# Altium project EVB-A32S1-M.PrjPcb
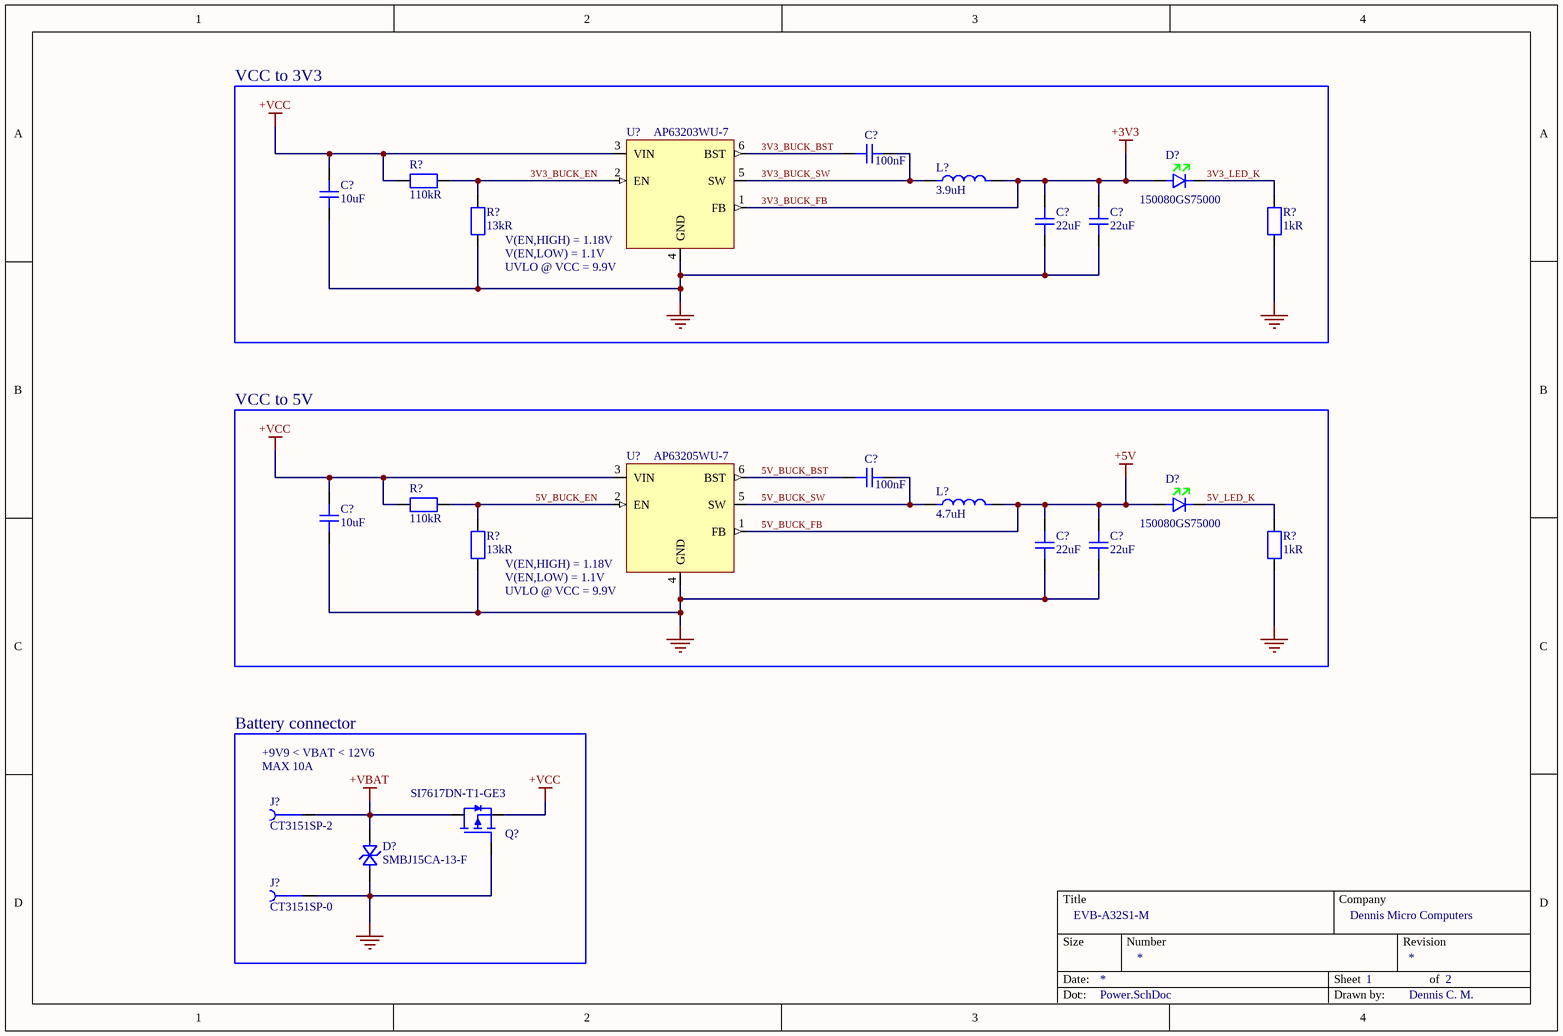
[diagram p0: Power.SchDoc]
CompanyName: Dennis Micro Computers; DrawnBy: Dennis C. M.; Title: EVB-A32S1-M
4 sheets, 55 parts. Net scope: flat (ports and power ports of the same name join across sheets).
Sheets:
  Power.SchDoc
  MCU.SchDoc
  Motor.SchDoc
  Sensing.SchDoc

## Sheet Power.SchDoc: EVB-A32S1-M
size A4; SheetNumber: 1; SheetTotal: 2

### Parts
(Parts that share a designator on the sheet are numbered #1, #2 ... from top to bottom, then left to right.)
C?#1  value 100nF  [C_Yageo_CC_0402_A]  (hidden comment: CC0402MRX5R6BB104)
C?#2  value 10uF  [C_Yageo_CC_0805_A]  (hidden comment: CC0805KRX5R7BB106)
C?#3  value 22uF  [C_Yageo_CC_0805_A]  (hidden comment: CC0805MKX5R6BB226)
C?#4  value 22uF  [C_Yageo_CC_0805_A]  (hidden comment: CC0805MKX5R6BB226)
C?#5  value 100nF  [C_Yageo_CC_0402_A]  (hidden comment: CC0402MRX5R6BB104)
C?#6  value 10uF  [C_Yageo_CC_0805_A]  (hidden comment: CC0805KRX5R7BB106)
C?#7  value 22uF  [C_Yageo_CC_0805_A]  (hidden comment: CC0805MKX5R6BB226)
C?#8  value 22uF  [C_Yageo_CC_0805_A]  (hidden comment: CC0805MKX5R6BB226)
D?#1  150080GS75000  [D_LED_We_150080GS75000]
D?#2  150080GS75000  [D_LED_We_150080GS75000]
D?#3  SMBJ15CA-13-F  [D_TVS_BI_Diodes_SMBJ15CA-13-F_A]
J?#1  CT3151SP-2  [J_CalTest_CT3151SP-2]
J?#2  CT3151SP-0  [J_CalTest_CT3151SP-0]
L?#1  value 3.9uH  [L_Murata_1255AY-XXXX=P3]  (hidden comment: 1255AY-3R9N=P3)
L?#2  value 4.7uH  [L_Murata_1255AY-XXXX=P3]  (hidden comment: 1255AY-4R7M=P3)
Q?  SI7617DN-T1-GE3  [Q_Vishay_SI7617DN-T1-GE3]
R?#1  value 110kR  [R_Yageo_RCL_0402_A]  (hidden comment: RC0402FR-07110KL)
R?#2  value 13kR  [R_Yageo_RCL_0402_A]  (hidden comment: RC0402FR-0713KL)
R?#3  value 1kR  [R_Yageo_RCL_0402_A]  (hidden comment: RC0402FR-071KL)
R?#4  value 110kR  [R_Yageo_RCL_0402_A]  (hidden comment: RC0402FR-07110KL)
R?#5  value 13kR  [R_Yageo_RCL_0402_A]  (hidden comment: RC0402FR-0713KL)
R?#6  value 1kR  [R_Yageo_RCL_0402_A]  (hidden comment: RC0402FR-071KL)
U?#1  AP63203WU-7  [U_Diodes_AP623xx]
U?#2  AP63205WU-7  [U_Diodes_AP623xx]

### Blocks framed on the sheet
VCC to 3V3: C?#1-C?#4 D?#1 L?#1 R?#1-R?#3 U?#1
VCC to 5V: C?#5-C?#8 D?#2 L?#2 R?#4-R?#6 U?#2
Battery connector: D?#3 J?#1 J?#2 Q?

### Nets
3V3_BUCK_FB: C?#3.2 C?#4.2 D?#1.1 L?#1.2 U?#1.1(FB)  [also labelled +3V3]
5V_BUCK_FB: C?#7.2 C?#8.2 D?#2.1 L?#2.2 U?#2.1(FB)  [also labelled +5V]
+VBAT: D?#3.1 J?#1.1 Q?.1(D)
+VCC: C?#2.2 C?#6.2 Q?.3(S) R?#1.2 R?#4.2 U?#1.3(VIN) U?#2.3(VIN)
GND: C?#2.1 C?#3.1 C?#4.1 C?#6.1 C?#7.1 C?#8.1 D?#3.2 J?#2.1 Q?.2(G) R?#2.1 R?#3.1 R?#5.1 R?#6.1 U?#1.4(GND) U?#2.4(GND)
3V3_BUCK_BST: C?#1.2 U?#1.6(BST)
3V3_BUCK_EN: R?#1.1 R?#2.2 U?#1.2(EN)
3V3_BUCK_SW: C?#1.1 L?#1.1 U?#1.5(SW)
3V3_LED_K: D?#1.2 R?#3.2
5V_BUCK_BST: C?#5.2 U?#2.6(BST)
5V_BUCK_EN: R?#4.1 R?#5.2 U?#2.2(EN)
5V_BUCK_SW: C?#5.1 L?#2.1 U?#2.5(SW)
5V_LED_K: D?#2.2 R?#6.2

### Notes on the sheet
- (near U?#1) V(EN,HIGH) = 1.18V
- V(EN,LOW) = 1.1V
- (near U?#1) UVLO @ VCC = 9.9V
- (near U?#2) V(EN,HIGH) = 1.18V
- (near U?#2) UVLO @ VCC = 9.9V
- +9V9 < VBAT < 12V6
- (near J?#1) MAX 10A

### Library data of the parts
C?#1 C?#5 = CMP-001-00009-8: Multilayer Ceramic Capacitor, 0.1 uF, 25 V, ± 20%, X7R, 0402 [1005 Metric]; Dielectric: X5R; Temperature Coefficient: 30ppm/°C; Voltage Rating: 10V
C?#2 C?#6 = CMP-001-00018-3: 0805 10 uF 16 V ±10% Tolerance X5R Multilayer Ceramic Chip Capacitor; Voltage Rating (DC): 16V
C?#3 C?#4 C?#7 C?#8 = CMP-001-00014-5: Multilayer Ceramic Capacitor, 22 uF, 10 V, ± 20%, X5R, 0805 [2012 Metric]; Voltage Rating (DC): 10V
D?#1 D?#2 = CMP-007-00000-6: WURTH ELEKTRONIK - 150080GS75000 - LED, Green, SMD, 0805, 30 mA, 3.2 V, 520 nm; Forward Current: 30mA; Forward Voltage: 3.2V; Luminous Intensity: 450mcd; Max Reverse Voltage (DC): 5V; Lens Transparency: Clear; Power Dissipation: 105mW; Lens Style: Clear,Flat,Rectangular; Lens Size: 1.25mm; Viewing Angle: 140°; Test Current: 20mA; Dominant Wavelength: 520nm; Lens Color: Colorless
D?#3 = CMP-004-00000-8: Tvs Diode, Bidir, 15V, 600W, Do-214Aa Rohs Compliant: Yes; Max Reverse Leakage Current: 5uA; Reverse Breakdown Voltage: 16.7V; Breakdown Voltage: 19.2V; Clamping Voltage: 24.4V; Power Line Protection: No; Max Surge Current: 24A; Number of Bidirectional Channels: 1; Test Current: 1mA; Value: 280pF; Polarity: Bidirectional; Diode Type: ZENER
J?#1 = CMP-002-00001-9: Conn 4mm Safety Banana Jack F 1 POS Solder RA Thru-Hole 1 Port Bag; pin to pad: 1>1+2+3+4; Body Material: Nylon,Polyamide,PA66; Insulation: Mating End Insulated; Gender: Female
J?#2 = CMP-002-00000-11: Conn 4mm Safety Banana Jack F 1 POS Solder RA Thru-Hole 1 Port Bag; pin to pad: 1>1+2+3+4; Body Material: Nylon,Polyamide,PA66; Insulation: Mating End Insulated; Gender: Female
L?#1 = CMP-006-00002-2: Inductor Power Shielded Wirewound 3.9uH 30% 100KHz Ferrite 4.2A 0.0264Ohm DCR 2424 T/R; DC Resistance (DCR): 26.4mR; Saturation Current: 4.7A
L?#2 = CMP-006-00001-5: Inductor Power Shielded Wirewound 4.7uH 20% 100KHz Ferrite 4A 0.0276Ohm DCR 2424 T/R; DC Resistance (DCR): 27.6mR; Current Rating: 4.5A
Q? = CMP-00000-6: P CHANNEL MOSFET, -30V, 35A; Transistor; Transistor Polarity: P Channel; Continuous Drain Current Id: -35A; Source; pin to pad: 1>5+6+7+8 2>4 3>1+2+3; Rise Time: 43ns; Drain to Source Resistance: 12.3mR; Turn-Off Delay Time: 30ns; Turn-On Delay Time: 40ns; Threshold Voltage: -2.5V; Max Power Dissipation: 52W; Fall Time: 11ns; Power Dissipation: 3.7W; Polarity: P-CHANNEL; Number of Elements: 1; Input Capacitance: 1.8nF; Gate to Source Voltage (Vgs): 25V
R?#1 R?#4 = CMP-009-00000-7: SMD Chip Resistor, 110 kOhm, ± 1%, 63 mW, 0402 [1005 Metric], Thick Film, General Purpose; Max Power Dissipation: 63mW; Voltage Rating (DC): 50V; Temperature Coefficient: 100ppm/°C
R?#2 R?#5 = CMP-009-00001-7: SMD Chip Resistor, 13 kOhm, ± 1%, 63 mW, 0402 [1005 Metric], Thick Film, General Purpose; Temperature Coefficient: 100ppm/°C; Voltage Rating: 50V; Max Power Dissipation: 63mW; Power Rating: 62.5mW
R?#3 R?#6 = CMP-009-00002-7: SMD Chip Resistor, 1 kOhm, ± 1%, 62.5 mW, 0402 [1005 Metric], Thick Film, General Purpose; Temperature Coefficient: 100ppm/°C; Voltage Rating (AC): 50V; Power Rating: 62.5mW; Max Power Dissipation: 63mW
U?#1 = CMP-019-00004-6: AP63203 Series 3.3 V 2 A SMT Fixed Low IQ Synchronous Buck - TSOT-26; Max Duty Cycle: 100%; Output Voltage: 3.3V; Number of Outputs: 1; Max Supply Voltage: 32V; Switching Frequency: 1.1MHz; Min Supply Voltage: 3.8V; Nominal Supply Current: 22uA; Output Current: 2A
U?#2 = CMP-019-00003-6: AP63205 Series 32 V 2 A 1.1 MHz Synchronous Buck Converter -TSOT-26; Number of Outputs: 1; Max Duty Cycle: 100%; Output Current: 2A; Switching Frequency: 1.1MHz; Max Supply Voltage: 32V; Output Voltage: 5V; Nominal Supply Current: 22uA; Min Supply Voltage: 3.8V

## Sheet MCU.SchDoc: EVB-A32S1-M
size A4; SheetNumber: 2; SheetTotal: 2
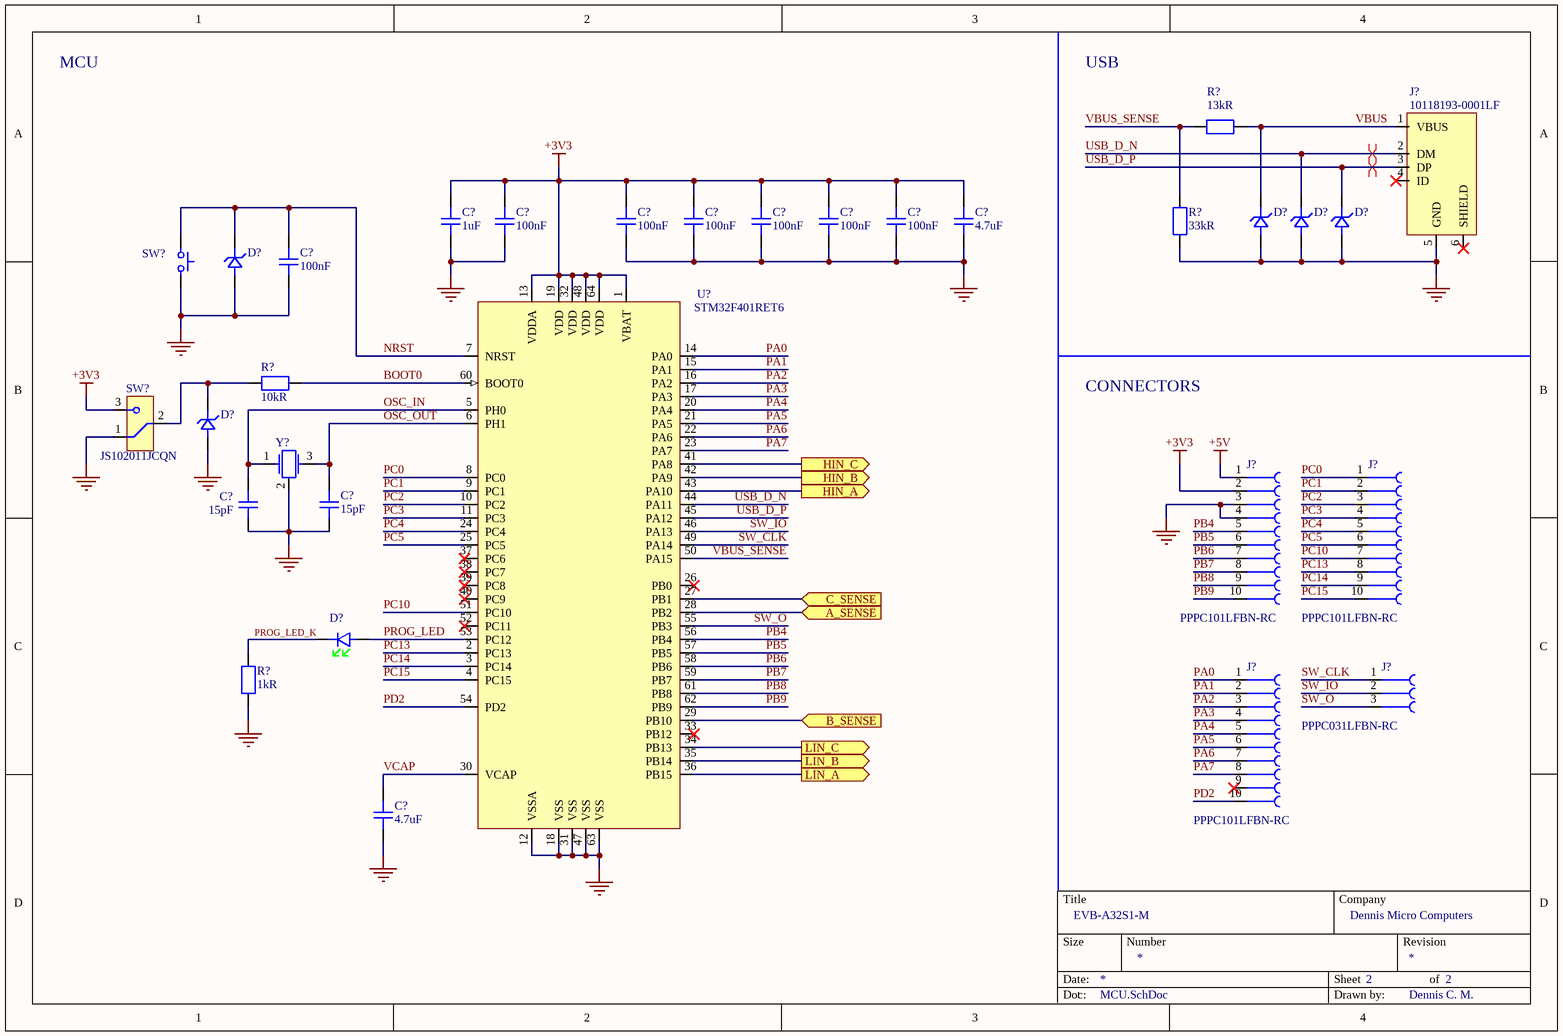
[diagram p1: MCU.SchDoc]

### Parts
(Parts that share a designator on the sheet are numbered #1, #2 ... from top to bottom, then left to right.)
C?#9  value 1uF  [C_Yageo_CC_0402_A]  (hidden comment: CC0402MRX5R6BB105)
C?#10  value 100nF  [C_Yageo_CC_0402_A]  (hidden comment: CC0402MRX5R6BB104)
C?#11  value 100nF  [C_Yageo_CC_0402_A]  (hidden comment: CC0402MRX5R6BB104)
C?#12  value 100nF  [C_Yageo_CC_0402_A]  (hidden comment: CC0402MRX5R6BB104)
C?#13  value 100nF  [C_Yageo_CC_0402_A]  (hidden comment: CC0402MRX5R6BB104)
C?#14  value 100nF  [C_Yageo_CC_0402_A]  (hidden comment: CC0402MRX5R6BB104)
C?#15  value 100nF  [C_Yageo_CC_0402_A]  (hidden comment: CC0402MRX5R6BB104)
C?#16  value 4.7uF  [C_Yageo_CC_0402_A]  (hidden comment: CC0402MRX5R6BB475)
C?#17  value 100nF  [C_Yageo_CC_0402_A]  (hidden comment: CC0402MRX5R6BB104)
C?#18  value 15pF  [C_Yageo_CC_0402_A]  (hidden comment: CC0402JRNPO9BN150)
C?#19  value 15pF  [C_Yageo_CC_0402_A]  (hidden comment: CC0402JRNPO9BN150)
C?#20  value 4.7uF  [C_Yageo_CC_0402_A]  (hidden comment: CC0402MRX5R6BB475)
D?#4  D5V0F1U2S9-7  [D_TVS_Uni_Diodes_SOD-923_B]  (value not drawn)
D?#5  D5V0F1U2S9-7  [D_TVS_Uni_Diodes_SOD-923_B]  (value not drawn)
D?#6  D5V0F1U2S9-7  [D_TVS_Uni_Diodes_SOD-923_B]  (value not drawn)
D?#7  D5V0F1U2S9-7  [D_TVS_Uni_Diodes_SOD-923_B]  (value not drawn)
D?#8  D5V0F1U2S9-7  [D_TVS_Uni_Diodes_SOD-923_B]  (value not drawn)
D?#9  150080GS75000  [D_LED_We_150080GS75000]  (value not drawn)
J?#3  10118193-0001LF  [J_USB_Micro-B_Amphenol_10118193-0001LF]
J?#4  PPPC101LFBN-RC  [J_Sullins_PPPC101LFBN-RC]
J?#5  PPPC101LFBN-RC  [J_Sullins_PPPC101LFBN-RC]
J?#6  PPPC031LFBN-RC  [J_Sullins_01x03_Socket_2.54mm]
J?#7  PPPC101LFBN-RC  [J_Sullins_PPPC101LFBN-RC]
R?#7  value 13kR  [R_Yageo_RCL_0402_A]  (hidden comment: RC0402FR-0713KL)
R?#8  value 33kR  [R_Yageo_RCL_0402_A]  (hidden comment: RC0402FR-0733KL)
R?#9  value 10kR  [R_Yageo_RCL_0402_A]  (hidden comment: RC0402FR-0710KL)
R?#10  value 1kR  [R_Yageo_RCL_0402_A]  (hidden comment: RC0402FR-071KL)
SW?#1  PTS647SN50SMTR2LFS  [SW_Tactitle_SPST_C&K_PTS647SN50SMTR2LFS]  (value not drawn)
SW?#2  JS102011JCQN  [SW_Slide_C&K_JS102011JCQN]
U?#3  STM32F401RET6  [U_STM32F401xD/xE_B]
Y?  ECS-240-12-37B-CKY-TR  [Y_Crystal_GND24_ECS_240-12-37B-CKY-TR]  (value not drawn)

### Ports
A_SENSE (in), B_SENSE (in), C_SENSE (in), HIN_A (out), HIN_B (out), HIN_C (out), LIN_A (out), LIN_B (out), LIN_C (out)

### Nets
+3V3: C?#9.2 C?#10.2 C?#11.2 C?#12.2 C?#13.2 C?#14.2 C?#15.2 C?#16.2 J?#4.2 SW?#2.3 U?#3.1(VBAT) U?#3.13(VDDA) U?#3.19(VDD) U?#3.32(VDD) U?#3.48(VDD) U?#3.64(VDD)  [project net 3V3_BUCK_FB]
+5V: J?#4.1  [project net 5V_BUCK_FB]
GND: C?#9.1 C?#10.1 C?#11.1 C?#12.1 C?#13.1 C?#14.1 C?#15.1 C?#16.1 C?#17.1 C?#18.1 C?#19.1 C?#20.1 D?#4.2 D?#5.2 D?#6.2 D?#7.2 D?#8.2 J?#3.5(GND) J?#4.3 J?#4.4 R?#8.1 R?#10.1 SW?#1.2 SW?#2.1 U?#3.12(VSSA) U?#3.18(VSS) U?#3.31(VSS) U?#3.47(VSS) U?#3.63(VSS) Y?.2
BOOT0: R?#9.2 U?#3.60(BOOT0)
NRST: C?#17.2 D?#7.1 SW?#1.1 U?#3.7(NRST)
OSC_IN: C?#18.2 U?#3.5(PH0) Y?.1
OSC_OUT: C?#19.2 U?#3.6(PH1) Y?.3
PA0: J?#7.1 U?#3.14(PA0)
PA1: J?#7.2 U?#3.15(PA1)
PA2: J?#7.3 U?#3.16(PA2)
PA3: J?#7.4 U?#3.17(PA3)
PA4: J?#7.5 U?#3.20(PA4)
PA5: J?#7.6 U?#3.21(PA5)
PA6: J?#7.7 U?#3.22(PA6)
PA7: J?#7.8 U?#3.23(PA7)
PB4: J?#4.5 U?#3.56(PB4)
PB5: J?#4.6 U?#3.57(PB5)
PB6: J?#4.7 U?#3.58(PB6)
PB7: J?#4.8 U?#3.59(PB7)
PB8: J?#4.9 U?#3.61(PB8)
PB9: J?#4.10 U?#3.62(PB9)
PC0: J?#5.1 U?#3.8(PC0)
PC1: J?#5.2 U?#3.9(PC1)
PC2: J?#5.3 U?#3.10(PC2)
PC3: J?#5.4 U?#3.11(PC3)
PC4: J?#5.5 U?#3.24(PC4)
PC5: J?#5.6 U?#3.25(PC5)
PC10: J?#5.7 U?#3.51(PC10)
PC13: J?#5.8 U?#3.2(PC13)
PC14: J?#5.9 U?#3.3(PC14)
PC15: J?#5.10 U?#3.4(PC15)
PD2: J?#7.10 U?#3.54(PD2)
PROG_LED: D?#9.1 U?#3.53(PC12)
PROG_LED_K: D?#9.2 R?#10.2
SW_CLK: J?#6.1 U?#3.49(PA14)
SW_IO: J?#6.2 U?#3.46(PA13)
SW_O: J?#6.3 U?#3.55(PB3)
USB_D_N: D?#5.1 J?#3.2(DM) U?#3.44(PA11)
USB_D_P: D?#6.1 J?#3.3(DP) U?#3.45(PA12)
VBUS: D?#4.1 J?#3.1(VBUS) R?#7.2
VBUS_SENSE: R?#7.1 R?#8.2 U?#3.50(PA15)
VCAP: C?#20.2 U?#3.30(VCAP)
NetD?#8_1: D?#8.1 R?#9.1 SW?#2.2
NetU?#3_27: U?#3.27(PB1) ; port C_SENSE
NetU?#3_28: U?#3.28(PB2) ; port A_SENSE
NetU?#3_29: U?#3.29(PB10) ; port B_SENSE
NetU?#3_34: U?#3.34(PB13) ; port LIN_C
NetU?#3_35: U?#3.35(PB14) ; port LIN_B
NetU?#3_36: U?#3.36(PB15) ; port LIN_A
NetU?#3_41: U?#3.41(PA8) ; port HIN_C
NetU?#3_42: U?#3.42(PA9) ; port HIN_B
NetU?#3_43: U?#3.43(PA10) ; port HIN_A

Not connected (* = marked no-connect by the designer): J?#3 4(ID)* 6(SHIELD)*; J?#7 9*; U?#3 26(PB0)* 33(PB12)* 37(PC6)* 38(PC7)* 39(PC8)* 40(PC9)* 52(PC11)*

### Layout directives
differential pair; differential pair class USB: USB_D_N, USB_D_P

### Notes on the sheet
- MCU
- USB
- CONNECTORS

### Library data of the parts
C?#9 = CMP-001-00016-7: Multilayer Ceramic Capacitor, 1 uF, 50 V, ± 10%, X5R, 0402 [1005 Metric]; Voltage Rating (DC): 10V; Tolerance: 20%; Temperature Coefficient: 30ppm/°C
C?#10-C?#15 C?#17 = CMP-001-00009-8: as C?#1 on sheet Power
C?#16 C?#20 = CMP-001-00015-8: Multilayer Ceramic Capacitor, 4.7 uF, 50 V, ± 10%, X5R, 0402 [1005 Metric]; Tolerance: 20%; Temperature Coefficient: 30ppm/°C; Voltage Rating (DC): 10V
C?#18 C?#19 = CMP-001-00017-9: Multilayer Ceramic Capacitor, 15 pF, 10 V, ± 5%, X7R, 0402 [1005 Metric]; Insulation Resistance: 100GR; Dielectric: C0G; Voltage Rating (DC): 50V; Temperature Coefficient: 30ppm/°C
D?#4-D?#8 = CMP-004-00003-1: Diode TVS Dual Uni-Dir 5.5V 250000W 2-Pin SOD-923 T/R; Max Power Dissipation: 250mW; ESD Protection: Yes; Max Reverse Leakage Current: 100nA; Capacitance: 0.5pF @ 1MHz; Max Surge Current: 1.5A; Diode Type: ZENER; Direction: Unidirectional; Breakdown Voltage: 6V; Clamping Voltage: 10V; Value: 5E-13F; Peak Pulse Power: 250kW; Number of Unidirectional Channels: 1
D?#9 = CMP-007-00000-6: WURTH ELEKTRONIK - 150080GS75000 - LED, Green, SMD, 0805, 30 mA, 3.2 V, 520 nm; Viewing Angle: 140°; Lens Transparency: Clear; Reverse Voltage: 5V; Lens Size: 1.25mm; Lens Color: Colorless; Lens Style: Clear,Flat,Rectangular; Power Dissipation: 105mW; Wavelength: 520nm; Forward Voltage: 3.2V; Test Current: 20mA; Forward Current: 30mA; Luminous Intensity: 450mcd
J?#3 = CMP-002-00002-7: Usb Connector, 5 Contact(S), Female, Right Angle, Surface Mount Terminal, Locking, Receptacle; Number of Contacts: 5; Current Rating: 1.8A; Connector Type: USB,Receptacle; Pitch: 650um; Number of Ports: 1; Voltage Rating: 100V; USB Standard: USB 2.0; Insulation Resistance: 1GR
J?#4 J?#5 J?#7 = CMP-002-00003-1: 10 Position Total Single Row 2.54 mm Pitch Straight Female Header; Voltage Rating: 250V; Number of Contacts: 10; Pitch: 0.1inch; Current Rating: 3A
J?#6 = CMP-002-00004-1: 3 Position Total Single Row 2.54 mm Pitch Straight Female Header; Voltage Rating: 250V; Number of Positions: 3; Pitch: 2.54mm
R?#7 = CMP-009-00001-7: SMD Chip Resistor, 13 kOhm, ± 1%, 63 mW, 0402 [1005 Metric], Thick Film, General Purpose; Voltage Rating (DC): 50V; Temperature Coefficient: 100ppm/°C; Max Power Dissipation: 63mW; Power Rating: 62.5mW
R?#8 = CMP-009-00005-8: SMD Chip Resistor, 33 kOhm, ± 1%, 63 mW, 0402 [1005 Metric], Thick Film, General Purpose; Power Rating: 63mW; Temperature Coefficient: 100ppm/°C; Voltage Rating (AC): 50V
R?#9 = CMP-009-00003-7: SMD Chip Resistor, 10 kOhm, ± 1%, 62.5 mW, 0402 [1005 Metric], Thick Film, General Purpose; Power Rating: 62.5mW; Max Power Dissipation: 63mW; Temperature Coefficient: 100ppm/°C; Voltage Rating (DC): 50V
R?#10 = CMP-009-00002-7: SMD Chip Resistor, 1 kOhm, ± 1%, 62.5 mW, 0402 [1005 Metric], Thick Film, General Purpose; Temperature Coefficient: 100ppm/°C; Max Power Dissipation: 63mW; Voltage Rating (AC): 50V; Power Rating: 62.5mW
SW?#1 = CMP-011-00000-10: Switch Tactile N.O. SPST Round Button Gull Wing 0.05A 12VDC 100000Cycles 0.98N SMD T/R; pin to pad: 1>1+2 2>3+4; Ratings: IP40; Switch Function: Off-Mom; Illumination Type: Non-Illuminated; Actuator Type: Standard; Number of Positions: 2; Operating Force: 100gf; Switch Travel: 0.25mm
SW?#2 = CMP-011-00001-7: JS Series Sub-Miniature Slide Switch SPDT On-On Top Slide 0.3A 6VDC J-Lead Surface Mount T/R; Voltage Rating (DC): 6V; Switch Travel: 2mm; Actuator Material: Nylon,Polyamide,PA46; Electrical Life: 5000Cycles; Actuator Type: Standard
U?#3 = CMP-020-00000-6: MCU 32-bit STM32 ARM Cortex M4 RISC 512KB Flash 1.8V/2.5V/3.3V 64-Pin LQFP Tray; Operating Supply Voltage: 3.3V; Peripherals: Brown-out Detect/Reset,POR,PWM,WDT,DMA; Nominal Supply Current: 1.8uA; Number of ADC Channels: 12; Interface: I2C,SPI,USB,IrDA,SDIO,UART,USART,LIN,I2S; Clock Frequency: 84MHz; Number of USB Channels: 1; Number of Timers/Counters: 8; Number of Channels: 16; Number of PWM Channels: 23; Number of UART Channels: 3; Number of Programmable I/O: 50; Watchdog Timer: Yes; Max Power Dissipation: 313mW; Min Supply Voltage: 1.7V; Data Bus Width: 32b; RAM Size: 96KB; Max Supply Voltage: 3.6V; Oscillator Type: Internal
Y? = CMP-003-00000-4: Crystal 24MHz ±10ppm (Tol) ±10ppm (Stability) 12pF FUND 50Ohm 4-Pin Mini-CSMD T/R; pin to pad: 2>2+4

## Sheet Motor.SchDoc: EVB-A32S1-M
size A4; SheetNumber: 3; SheetTotal: 3

## Sheet Sensing.SchDoc: EVB-A32S1-M
size A4; Author: Dennis C. M; CompanyName: Dennis Micro Computers; DrawnBy: Dennis C. M.; SheetNumber: 4; SheetTotal: 4; Size: A4

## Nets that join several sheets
3V3_BUCK_FB: Power (5 pins), MCU (16 pins)
5V_BUCK_FB: Power (5 pins), MCU (J?#4.1)
GND: Power (15 pins), MCU (30 pins)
